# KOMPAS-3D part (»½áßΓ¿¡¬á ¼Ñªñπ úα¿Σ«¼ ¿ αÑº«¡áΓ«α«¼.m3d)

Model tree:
1. Эскиз:1
2. Операция выдавливания:1
     Расстояние 1 = 6
3. Эскиз:2
4. Вырезать элемент выдавливания:1
     Расстояние 1 = 10
